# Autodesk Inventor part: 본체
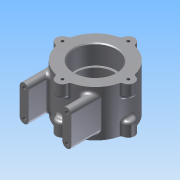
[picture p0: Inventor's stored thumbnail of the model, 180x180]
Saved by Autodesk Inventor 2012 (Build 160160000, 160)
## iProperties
Created: 2007-01
Part Number: 본체
Material: Default
Document SubType Name: Modeling
Designer: net
Density: 1 g/cm^3
Author: net
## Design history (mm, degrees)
sketch "스케치1"
  geometry: C1 r 37 at (0, 0); 1 further point
  constraints: 1 centre point, 1 coincident
  dimensions: "d0" = 74 diameter of C1
extrude "돌출1" new body sketch "스케치1" distance "d1" = 52; taper "d2" = 0 deg
node "작업 평면2"
sketch "스케치3"
  geometry: L1 (-37, 0)-(-37, 52) reference; L2 (37, 0)-(37, 52) reference; L3 (-29, 41)-(-29, 11); L4 (-29, 11)-(-29, 41); L5 (-19, 11)-(-19, 41); L6 (19, 11)-(19, 41); L7 (29, 41)-(29, 11); L8 (-19, 26)-(19, 26); A1 r 5 centre (-24, 11) between (-29, 11) and (-19, 11); A2 r 5 centre (-24, 41) between (-19, 41) and (-29, 41); A3 r 5 centre (24, 41) between (29, 41) and (19, 41); A4 r 5 centre (24, 11) between (19, 11) and (29, 11); 3 further points
  constraints: 13 end point, 8 point on circle, 8 tangent, 5 parallel, 4 centre point, 4 midpoint, 1 equal radius, 1 horizontal, 1 horizontal alignment, 1 vertical alignment
  dimensions: "d5" = 48 distance of A4.centre A1.centre; "d7" = 10 distance between parallel lines of L6 L7; "d153" = 40 dimension on A4 A3
extrude "돌출2" join sketch "스케치3" distance "d9" = 56; taper "d10" = 0 deg
sketch "스케치4"
  geometry: C1 r 7 at (0, 37); 1 further point
  constraints: 2 vertical alignment, 1 centre point, 1 other
  dimensions: "d11" = 14 diameter of C1
extrude "돌출3" join sketch "스케치4" distance "d12" = 15; taper "d13" = 0 deg
sketch "스케치5"
  geometry: C1 r 7 at (0, 37); A1 r 37 centre (0, 0) between (6.969, 36.338) and (-6.969, 36.338) reference; A2 r 7 centre (0, 37) between (6.969, 36.338) and (-6.969, 36.338) reference
  constraints: 1 centre point, 1 coincident
  dimensions: "d17" = 14 diameter of C1
extrude "돌출4" join sketch "스케치5" distance "d18" = 15; taper "d19" = 0 deg
sketch "스케치6"
  geometry: C1 r 23.5 at (0, 0); A1 r 37 centre (0, 0) between (6.969, -36.338) and (36.338, -6.969) reference
  constraints: 1 centre point, 1 coincident
  dimensions: "d23" = 47 diameter of C1
extrude "돌출5" cut sketch "스케치6" distance "d24" = 22; taper "d25" = 0 deg
sketch "스케치7"
  geometry: C1 r 23.5 at (0, 0); A1 r 37 centre (0, 0) between (36.338, 6.969) and (6.969, 36.338) reference
  constraints: 1 centre point, 1 coincident
  dimensions: "d26" = 47 diameter of C1
extrude "돌출6" cut sketch "스케치7" distance "d27" = 22; taper "d28" = 0 deg
sketch "스케치8"
  geometry: C1 r 23.5 at (0, 0) reference; C2 r 21 at (0, 0)
  constraints: 1 centre point, 1 coincident
  dimensions: "d29" = 42 diameter of C2
extrude "돌출7" cut sketch "스케치8" stored distance "d30" = 22; taper "d31" = 0 deg
hole "구멍1" diameter "d34" = 3.242; stored, may be unused: countersink angle "d38" = 90 deg, drill point angle "d40" = 118 deg; dims "d32" = 10, "d33" = 10, "d35" = 8, "d36" = 4, "d37" = 2, "d39" = 11
hole "구멍2" diameter "d43" = 3.242; stored, may be unused: countersink angle "d47" = 90 deg, drill point angle "d49" = 118 deg; dims "d41" = 10, "d42" = 10, "d44" = 8, "d45" = 4, "d46" = 2, "d48" = 11
hole "구멍3" diameter "d52" = 3.242; stored, may be unused: countersink angle "d56" = 90 deg, drill point angle "d58" = 118 deg; dims "d50" = 10, "d51" = 10, "d53" = 8, "d54" = 4, "d55" = 2, "d57" = 11
hole "구멍4" diameter "d61" = 3.242; stored, may be unused: countersink angle "d65" = 90 deg, drill point angle "d67" = 118 deg; dims "d59" = 10, "d60" = 10, "d62" = 8, "d63" = 4, "d64" = 2, "d66" = 11
hole "구멍5" diameter "d70" = 3.242; stored, may be unused: countersink angle "d74" = 90 deg, drill point angle "d76" = 118 deg; dims "d68" = 10, "d69" = 10, "d71" = 8, "d72" = 4, "d73" = 2, "d75" = 11
hole "구멍6" diameter "d79" = 3.242; stored, may be unused: countersink angle "d83" = 90 deg, drill point angle "d85" = 118 deg; dims "d77" = 10, "d78" = 10, "d80" = 8, "d81" = 4, "d82" = 2, "d84" = 11
hole "구멍7" diameter "d88" = 3.242; stored, may be unused: countersink angle "d92" = 90 deg, drill point angle "d94" = 118 deg; dims "d86" = 10, "d87" = 10, "d89" = 8, "d90" = 4, "d91" = 2, "d93" = 11
hole "구멍8" diameter "d97" = 3.242; stored, may be unused: countersink angle "d101" = 90 deg, drill point angle "d103" = 118 deg; dims "d95" = 10, "d96" = 10, "d98" = 8, "d99" = 4, "d100" = 2, "d102" = 11
hole "구멍9" diameter "d106" = 4.134; stored, may be unused: countersink angle "d110" = 90 deg, drill point angle "d112" = 118 deg; dims "d104" = 10, "d105" = 10, "d107" = 6, "d108" = 4, "d109" = 2, "d111" = 8
hole "구멍10" diameter "d115" = 4.134; stored, may be unused: countersink angle "d119" = 90 deg, drill point angle "d121" = 118 deg; dims "d113" = 10, "d114" = 10, "d116" = 6, "d117" = 4, "d118" = 2, "d120" = 8
hole "구멍11" diameter "d124" = 4.134; stored, may be unused: countersink angle "d128" = 90 deg, drill point angle "d130" = 118 deg; dims "d122" = 10, "d123" = 10, "d125" = 6, "d126" = 4, "d127" = 2, "d129" = 8
hole "구멍12" diameter "d133" = 4.134; stored, may be unused: countersink angle "d137" = 90 deg, drill point angle "d139" = 118 deg; dims "d131" = 10, "d132" = 10, "d134" = 6, "d135" = 4, "d136" = 2, "d138" = 8
node "작업 평면3"
sketch "스케치9"
  geometry: L1 (29, -22.978)-(29, -56) reference; L2 (29, -56)-(19, -56) reference; L3 (19, -56)-(19, -31.749) reference; L4 (-19, -31.749)-(-19, -56) reference; L5 (-19, -56)-(-29, -56) reference; L6 (-29, -56)-(-29, -22.978) reference; L7 (0, 0)-(26.163, 26.163); L8 (0, 0)-(37, 0); C1 r 21 at (0, 0) reference; A1 r 37 centre (0, 0) between (29, -22.978) and (-29, -22.978) reference; A2 r 37 centre (0, 0) between (-19, -31.749) and (19, -31.749) reference; 1 further point
  constraints: 4 end point, 2 point on circle, 1 perpendicular
  dimensions: "d141" = 45 deg angle of L8 L7
  node "절단 모서리 투영1"
node "작업 평면4"
sketch "스케치10"
  geometry: L1 (-20.767, -26)-(20.767, -26) reference; 3 further points
  constraints: 1 other
  dimensions: "d142" = 26 distance from line of L1 point (0, 0); "d143" = 0 distance of point (0, 0) point (0, 0)
feature "엠보싱1" sketch "스케치10" dims "d0" = 74, "d144" = 0.5, "d145" = 0
fillet "모깎기1" dims "d146" = 3
fillet "모깎기2" dims "d147" = 3
fillet "모깎기3" dims "d148" = 3
fillet "모깎기4" dims "d149" = 0.3
chamfer "모따기1" distance "d150" = 1; stored, may be unused: second distance "d151" = 2, angle "d152" = 45 deg
node "솔리드1"
pattern_circular "원형 패턴1" dims angle "d15" = 360 deg
pattern_circular "원형 패턴2" dims angle "d21" = 360 deg
node "투영된 루프1"
other parameters: "d4" = -56, "d140" = 26
